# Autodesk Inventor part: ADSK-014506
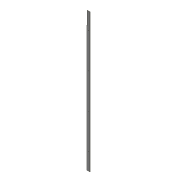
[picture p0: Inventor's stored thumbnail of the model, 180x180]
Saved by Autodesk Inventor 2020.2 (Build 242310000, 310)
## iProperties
Created: 2019-10
Part Number: ADSK-014506
Material: 1.0312 DC05
Document SubType Name: Blech
Designer: lutzd
Mass: 636.322 g
Surface Area: 4376.7 cm^2
Volume: 636.322 cm^3
Density: 1 g/cm^3
Sheet Metal Rule: Stahlblech 1.0312 - DC05 -   3.0 mm
Appearance: Stahl
Flat Pattern Width: 10.0786 cm
Flat Pattern Length: 210 cm
Flat Pattern Area: 2116.5 cm^2
Sheet Metal Width: 100,786 mm
Sheet Metal Length: 2100,000 mm
Sheet Metal Area: 211650,264 mm^2
VLDS_Profile: Default Part
VLDS_TimeStamp: 2016-07-29
VLDS_FailCnt: 0
VLDS_AcceptCnt: 0
Dimensions: 53x2100x53 mm
Semi finished: Stahlblech 1.0312 - DC05 -   3.0 mm
Mass: 0,636 kg
DocNumber: ADSK-014506
Folder: 01 - Themengebiete\Simplification\01 - Packaging machine\Parts\
Original: C:\AB_Vault\CAD\01 - Themengebiete\Simplification\01 - Packaging machine\ADSK-014367.ipt
VDS_Category: 3D Komponenten
VDS_NumSchm: Autodesk
G_L: 100,8x2100 mm
Thickness: 3,000 mm
VLT_Material: 1.0312 DC05
Title: rail
Author: lutzd
Revision Number: -
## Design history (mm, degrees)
node "Konturlasche1"
  sketch "Skizze1"
    geometry: L1 (0, 0)-(0, 50); L2 (0, 0)-(50, 0)
    constraints: 4 end point, 1 horizontal, 1 vertical
    dimensions: "d0" = 50 distance of L1.start L2.end; "d1" = 50 distance of L1.start L1.end
sketch "Skizze2"
  geometry: L1 (10.6, 1050)-(-63.6, 1050) reference; L2 (0, 2100)-(0, 0) reference; L3 (-25, 255)-(-25, 1845); 4 further points
  constraints: 3 point on line, 2 end point, 1 midpoint, 1 vertical
  dimensions: "d22" = 1590 distance of L3.start L3.end; "d23" = 530 distance of L3.end point (-25, 1315) (= 0.333333 x d22); "d24" = 530 distance of L3.start point (-25, 785) (= 0.333333 x d22); "d25" = 25 distance between parallel lines of L2 L3
hole "Bohrung1" sketch "Skizze2" at (-25, 785), (-25, 1315), (-25, 255), (-25, 1845) diameter "d15" = 6.6; stored, may be unused: countersink angle "d19" = 90 deg, drill point angle "d21" = 118 deg; dims "d16" = 16, "d17" = 12.6, "d18" = 2, "d20" = 3 (= Stärke)
node "Volumenkörper1"
feature "Grobblech1" dims "d2" = 3 (= Stärke), "d3" = 3 (= BreiteBiegungsfreistellung), "d4" = 1.5 (= TiefeBiegungsfreistellung), "d5" = 6 (= MinimalRest), "d6" = 3 (= Übergangsradius), "d7" = 2100, "d8" = 3 (= Biegeradius), "d9" = 3, "d10" = 12 (= GrößeEckenfreistellung), "d11" = 3 (= Abstandsgröße), "d12" = 3 (= JacobiRadiusGröße), "AbstandVerbindung" = 0.01
feature "Biegung1" dims "d2" = 3 (= Stärke), "d3" = 3 (= BreiteBiegungsfreistellung), "d4" = 1.5 (= TiefeBiegungsfreistellung), "d5" = 6 (= MinimalRest), "d6" = 3 (= Übergangsradius), "d8" = 3 (= Biegeradius), "d9" = 3, "AbstandVerbindung" = 0.01
feature "Ecke1" dims "d9" = 3, "d10" = 12 (= GrößeEckenfreistellung), "d11" = 3 (= Abstandsgröße), "d12" = 3 (= JacobiRadiusGröße)
feature "Definition1"
other parameters: "Stärke" = 3 (derived), "KFaktor" = 4.4, "Biegeradius" = 3 (= Stärke), "BreiteBiegungsfreistellung" = 3 (= Stärke), "TiefeBiegungsfreistellung" = 1.5 (= 0.5 x Stärke), "GrößeEckenfreistellung" = 12 (= 4 x Stärke), "MinimalRest" = 6 (= 2 x Stärke), "Übergangsradius" = 3 (= Biegeradius), "JacobiRadiusGröße" = 3 (= Biegeradius), "Abstandsgröße" = 3 (= Stärke), "Abstandsgröße" = 3, "Biegeradius" = 3, "BreiteBiegungsfreistellung" = 3, "GrößeEckenfreistellung" = 12, "JacobiRadiusGröße" = 3, "MinimalRest" = 6, "Stärke" = 3, "TiefeBiegungsfreistellung" = 1.5, "Übergangsradius" = 3
